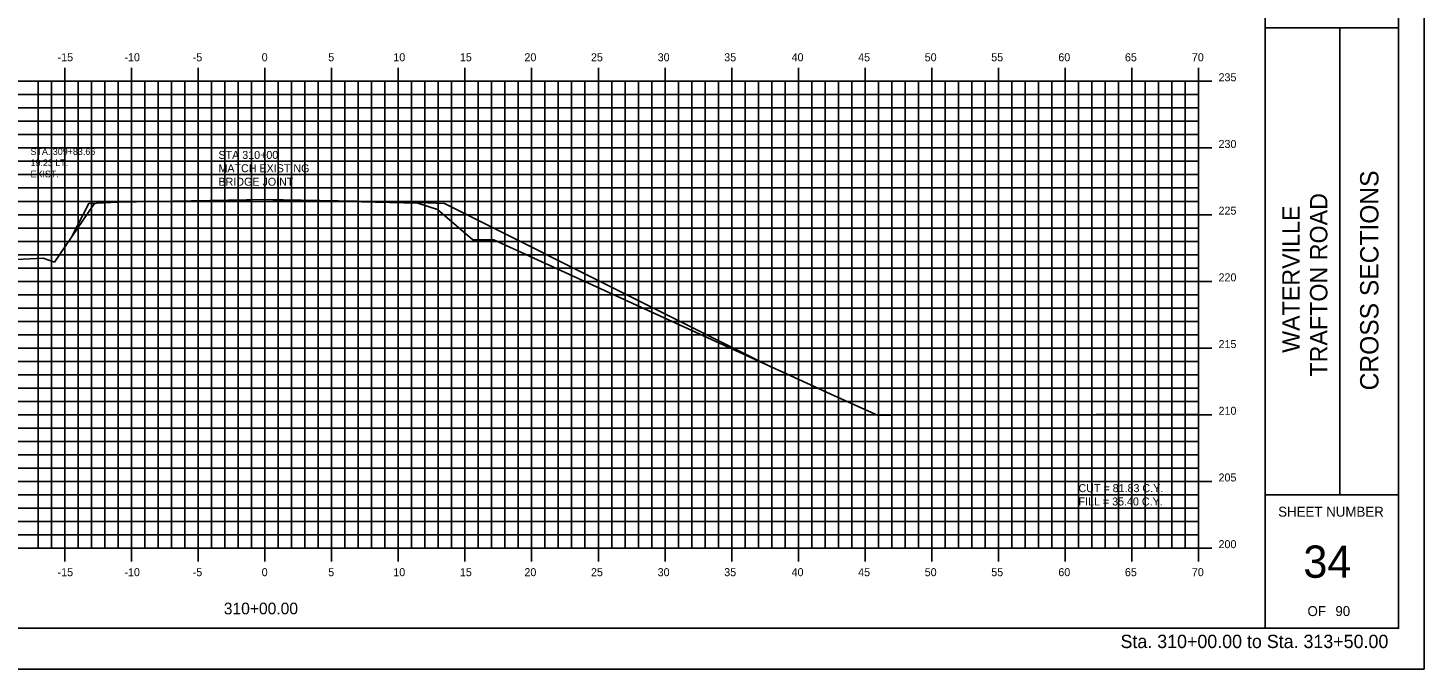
# Model space of a CAD drawing. Extents: x 1138098 to 1138268, y 608981 to 609091.
# Drawn here: x 1138163.2 to 1138267.8, y 608981.3 to 609029.3 of the extents above; entities that cross this region are included whole.
import ezdxf

# ---------------------------------------------------------------- set-up
doc = ezdxf.new("R2010")
doc.units = 0
for name, color, linetype in [('ANNOTATION', 7, 'Continuous'), ('BORDER', 7, 'Continuous'), ('D_Roadway_Centerline', 7, 'Continuous'), ('D_Text_Monospaced', 7, 'Continuous'), ('D_Text_Standard', 7, 'Continuous'), ('H_V ANNOTATION', 7, 'Continuous'), ('HIGHWAY_TITLE', 7, 'Continuous'), ('MAJOR', 7, 'Continuous'), ('MINOR', 7, 'Continuous'), ('PLOT BOUNDARY', 7, 'Continuous'), ('S_Roadway_Centerline', 7, 'Continuous')]:
    doc.layers.add(name, color=color, linetype=linetype)

msp = doc.modelspace()

# ---------------------------------------------------------------- linework, layer by layer
msp.add_lwpolyline([(1138166.45, 609013.7), (1138167.73, 609016.18), (1138167.73, 609016.18), (1138169.92, 609016.27), (1138180.92, 609016.49), (1138191.92, 609016.27), (1138194.38, 609016.17), (1138199.48, 609013.62), (1138204.46, 609011.13), (1138218.9, 609003.91)])
at = {"layer": 'BORDER'}
for p, q in [((1138255.92, 608984.34), (1138255.92, 609089.34)), ((1138255.92, 609029.34), (1138265.92, 609029.34)), ((1138261.51, 608994.34), (1138261.51, 609029.34)), ((1138255.92, 608994.34), (1138265.92, 608994.34))]:
    msp.add_line(p, q, dxfattribs=at)
msp.add_lwpolyline([(1138105.92, 608984.34), (1138265.92, 608984.34), (1138265.92, 609089.34), (1138105.92, 609089.34)], close=True, dxfattribs=at)
at = {"layer": 'MAJOR'}
for p, q in [((1138165.92, 609026.34), (1138165.92, 609025.34)), ((1138170.92, 609026.34), (1138170.92, 609025.34)), ((1138175.92, 609026.34), (1138175.92, 609025.34)), ((1138180.92, 609026.34), (1138180.92, 609025.34)), ((1138185.92, 609026.34), (1138185.92, 609025.34)), ((1138190.92, 609026.34), (1138190.92, 609025.34)), ((1138195.92, 609026.34), (1138195.92, 609025.34)), ((1138200.92, 609026.34), (1138200.92, 609025.34)), ((1138205.92, 609026.34), (1138205.92, 609025.34)), ((1138210.92, 609026.34), (1138210.92, 609025.34)), ((1138215.92, 609026.34), (1138215.92, 609025.34)), ((1138220.92, 609026.34), (1138220.92, 609025.34)), ((1138225.92, 609026.34), (1138225.92, 609025.34)), ((1138230.92, 609026.34), (1138230.92, 609025.34)), ((1138235.92, 609026.34), (1138235.92, 609025.34)), ((1138240.92, 609026.34), (1138240.92, 609025.34)), ((1138245.92, 609026.34), (1138245.92, 609025.34)), ((1138250.92, 609026.34), (1138250.92, 609025.34)), ((1138110.92, 609025.34), (1138250.92, 609025.34)), ((1138110.92, 609025.34), (1138250.92, 609025.34)), ((1138165.92, 608990.34), (1138165.92, 609025.34)), ((1138170.92, 608990.34), (1138170.92, 609025.34)), ((1138175.92, 608990.34), (1138175.92, 609025.34)), ((1138180.92, 608990.34), (1138180.92, 609025.34)), ((1138185.92, 608990.34), (1138185.92, 609025.34)), ((1138190.92, 608990.34), (1138190.92, 609025.34)), ((1138195.92, 608990.34), (1138195.92, 609025.34)), ((1138200.92, 608990.34), (1138200.92, 609025.34)), ((1138205.92, 608990.34), (1138205.92, 609025.34)), ((1138210.92, 608990.34), (1138210.92, 609025.34)), ((1138215.92, 608990.34), (1138215.92, 609025.34)), ((1138220.92, 608990.34), (1138220.92, 609025.34)), ((1138225.92, 608990.34), (1138225.92, 609025.34)), ((1138230.92, 608990.34), (1138230.92, 609025.34)), ((1138235.92, 608990.34), (1138235.92, 609025.34)), ((1138240.92, 608990.34), (1138240.92, 609025.34)), ((1138245.92, 608990.34), (1138245.92, 609025.34)), ((1138251.92, 609025.34), (1138249.92, 609025.34)), ((1138250.92, 608990.34), (1138250.92, 609025.34)), ((1138250.92, 608990.34), (1138250.92, 609025.34)), ((1138110.92, 609020.34), (1138250.92, 609020.34)), ((1138251.92, 609020.34), (1138249.92, 609020.34)), ((1138110.92, 609015.34), (1138250.92, 609015.34)), ((1138251.92, 609015.34), (1138249.92, 609015.34)), ((1138110.92, 609010.34), (1138250.92, 609010.34)), ((1138251.92, 609010.34), (1138249.92, 609010.34)), ((1138110.92, 609005.34), (1138250.92, 609005.34)), ((1138251.92, 609005.34), (1138249.92, 609005.34)), ((1138110.92, 609000.34), (1138250.92, 609000.34)), ((1138251.92, 609000.34), (1138249.92, 609000.34)), ((1138110.92, 608995.34), (1138250.92, 608995.34)), ((1138251.92, 608995.34), (1138249.92, 608995.34)), ((1138110.92, 608990.34), (1138250.92, 608990.34)), ((1138110.92, 608990.34), (1138250.92, 608990.34)), ((1138165.92, 608989.33), (1138165.92, 608990.34)), ((1138170.92, 608989.33), (1138170.92, 608990.34)), ((1138175.92, 608989.33), (1138175.92, 608990.34)), ((1138180.92, 608989.33), (1138180.92, 608990.34)), ((1138185.92, 608989.33), (1138185.92, 608990.34)), ((1138190.92, 608989.33), (1138190.92, 608990.34)), ((1138195.92, 608989.33), (1138195.92, 608990.34)), ((1138200.92, 608989.33), (1138200.92, 608990.34)), ((1138205.92, 608989.33), (1138205.92, 608990.34)), ((1138210.92, 608989.33), (1138210.92, 608990.34)), ((1138215.92, 608989.33), (1138215.92, 608990.34)), ((1138220.92, 608989.33), (1138220.92, 608990.34)), ((1138225.92, 608989.33), (1138225.92, 608990.34)), ((1138230.92, 608989.33), (1138230.92, 608990.34)), ((1138235.92, 608989.33), (1138235.92, 608990.34)), ((1138240.92, 608989.33), (1138240.92, 608990.34)), ((1138245.92, 608989.33), (1138245.92, 608990.34)), ((1138251.92, 608990.34), (1138249.92, 608990.34)), ((1138250.92, 608989.33), (1138250.92, 608990.34))]:
    msp.add_line(p, q, dxfattribs=at)
at = {"layer": 'MINOR'}
for p, q in [((1138163.92, 608990.34), (1138163.92, 609025.34)), ((1138164.92, 608990.34), (1138164.92, 609025.34)), ((1138166.92, 608990.34), (1138166.92, 609025.34)), ((1138167.92, 608990.34), (1138167.92, 609025.34)), ((1138168.92, 608990.34), (1138168.92, 609025.34)), ((1138169.92, 608990.34), (1138169.92, 609025.34)), ((1138171.92, 608990.34), (1138171.92, 609025.34)), ((1138172.92, 608990.34), (1138172.92, 609025.34)), ((1138173.92, 608990.34), (1138173.92, 609025.34)), ((1138174.92, 608990.34), (1138174.92, 609025.34)), ((1138176.92, 608990.34), (1138176.92, 609025.34)), ((1138177.92, 608990.34), (1138177.92, 609025.34)), ((1138178.92, 608990.34), (1138178.92, 609025.34)), ((1138179.92, 608990.34), (1138179.92, 609025.34)), ((1138181.92, 608990.34), (1138181.92, 609025.34)), ((1138182.92, 608990.34), (1138182.92, 609025.34)), ((1138183.92, 608990.34), (1138183.92, 609025.34)), ((1138184.92, 608990.34), (1138184.92, 609025.34)), ((1138186.92, 608990.34), (1138186.92, 609025.34)), ((1138187.92, 608990.34), (1138187.92, 609025.34)), ((1138188.92, 608990.34), (1138188.92, 609025.34)), ((1138189.92, 608990.34), (1138189.92, 609025.34)), ((1138191.92, 608990.34), (1138191.92, 609025.34)), ((1138192.92, 608990.34), (1138192.92, 609025.34)), ((1138193.92, 608990.34), (1138193.92, 609025.34)), ((1138194.92, 608990.34), (1138194.92, 609025.34)), ((1138196.92, 608990.34), (1138196.92, 609025.34)), ((1138197.92, 608990.34), (1138197.92, 609025.34)), ((1138198.92, 608990.34), (1138198.92, 609025.34)), ((1138199.92, 608990.34), (1138199.92, 609025.34)), ((1138201.92, 608990.34), (1138201.92, 609025.34)), ((1138202.92, 608990.34), (1138202.92, 609025.34)), ((1138203.92, 608990.34), (1138203.92, 609025.34)), ((1138204.92, 608990.34), (1138204.92, 609025.34)), ((1138206.92, 608990.34), (1138206.92, 609025.34)), ((1138207.92, 608990.34), (1138207.92, 609025.34)), ((1138208.92, 608990.34), (1138208.92, 609025.34)), ((1138209.92, 608990.34), (1138209.92, 609025.34)), ((1138211.92, 608990.34), (1138211.92, 609025.34)), ((1138212.92, 608990.34), (1138212.92, 609025.34)), ((1138213.92, 608990.34), (1138213.92, 609025.34)), ((1138214.92, 608990.34), (1138214.92, 609025.34)), ((1138216.92, 608990.34), (1138216.92, 609025.34)), ((1138217.92, 608990.34), (1138217.92, 609025.34)), ((1138218.92, 608990.34), (1138218.92, 609025.34)), ((1138219.92, 608990.34), (1138219.92, 609025.34)), ((1138221.92, 608990.34), (1138221.92, 609025.34)), ((1138222.92, 608990.34), (1138222.92, 609025.34)), ((1138223.92, 608990.34), (1138223.92, 609025.34)), ((1138224.92, 608990.34), (1138224.92, 609025.34)), ((1138226.92, 608990.34), (1138226.92, 609025.34)), ((1138227.92, 608990.34), (1138227.92, 609025.34)), ((1138228.92, 608990.34), (1138228.92, 609025.34)), ((1138229.92, 608990.34), (1138229.92, 609025.34)), ((1138231.92, 608990.34), (1138231.92, 609025.34)), ((1138232.92, 608990.34), (1138232.92, 609025.34)), ((1138233.92, 608990.34), (1138233.92, 609025.34)), ((1138234.92, 608990.34), (1138234.92, 609025.34)), ((1138236.92, 608990.34), (1138236.92, 609025.34)), ((1138237.92, 608990.34), (1138237.92, 609025.34)), ((1138238.92, 608990.34), (1138238.92, 609025.34)), ((1138239.92, 608990.34), (1138239.92, 609025.34)), ((1138241.92, 608990.34), (1138241.92, 609025.34)), ((1138242.92, 608990.34), (1138242.92, 609025.34)), ((1138243.92, 608990.34), (1138243.92, 609025.34)), ((1138244.92, 608990.34), (1138244.92, 609025.34)), ((1138246.92, 608990.34), (1138246.92, 609025.34)), ((1138247.92, 608990.34), (1138247.92, 609025.34)), ((1138248.92, 608990.34), (1138248.92, 609025.34)), ((1138249.92, 608990.34), (1138249.92, 609025.34)), ((1138110.92, 609024.34), (1138250.92, 609024.34)), ((1138250.92, 609024.34), (1138249.92, 609024.34)), ((1138110.92, 609023.34), (1138250.92, 609023.34)), ((1138250.92, 609023.34), (1138249.92, 609023.34)), ((1138110.92, 609022.34), (1138250.92, 609022.34)), ((1138250.92, 609022.34), (1138249.92, 609022.34)), ((1138110.92, 609021.34), (1138250.92, 609021.34)), ((1138250.92, 609021.34), (1138249.92, 609021.34)), ((1138110.92, 609019.34), (1138250.92, 609019.34)), ((1138250.92, 609019.34), (1138249.92, 609019.34)), ((1138110.92, 609018.34), (1138250.92, 609018.34)), ((1138250.92, 609018.34), (1138249.92, 609018.34)), ((1138110.92, 609017.34), (1138250.92, 609017.34)), ((1138250.92, 609017.34), (1138249.92, 609017.34)), ((1138110.92, 609016.34), (1138250.92, 609016.34)), ((1138250.92, 609016.34), (1138249.92, 609016.34)), ((1138110.92, 609014.34), (1138250.92, 609014.34)), ((1138250.92, 609014.34), (1138249.92, 609014.34)), ((1138110.92, 609013.34), (1138250.92, 609013.34)), ((1138250.92, 609013.34), (1138249.92, 609013.34)), ((1138110.92, 609012.34), (1138250.92, 609012.34)), ((1138250.92, 609012.34), (1138249.92, 609012.34)), ((1138110.92, 609011.34), (1138250.92, 609011.34)), ((1138250.92, 609011.34), (1138249.92, 609011.34)), ((1138110.92, 609009.34), (1138250.92, 609009.34)), ((1138250.92, 609009.34), (1138249.92, 609009.34)), ((1138110.92, 609008.34), (1138250.92, 609008.34)), ((1138250.92, 609008.34), (1138249.92, 609008.34)), ((1138110.92, 609007.34), (1138250.92, 609007.34)), ((1138250.92, 609007.34), (1138249.92, 609007.34)), ((1138110.92, 609006.34), (1138250.92, 609006.34)), ((1138250.92, 609006.34), (1138249.92, 609006.34)), ((1138110.92, 609004.34), (1138250.92, 609004.34)), ((1138250.92, 609004.34), (1138249.92, 609004.34)), ((1138110.92, 609003.34), (1138250.92, 609003.34)), ((1138250.92, 609003.34), (1138249.92, 609003.34)), ((1138110.92, 609002.34), (1138250.92, 609002.34)), ((1138250.92, 609002.34), (1138249.92, 609002.34)), ((1138110.92, 609001.34), (1138250.92, 609001.34)), ((1138250.92, 609001.34), (1138249.92, 609001.34)), ((1138110.92, 608999.34), (1138250.92, 608999.34)), ((1138250.92, 608999.34), (1138249.92, 608999.34)), ((1138110.92, 608998.34), (1138250.92, 608998.34)), ((1138250.92, 608998.34), (1138249.92, 608998.34)), ((1138110.92, 608997.34), (1138250.92, 608997.34)), ((1138250.92, 608997.34), (1138249.92, 608997.34)), ((1138110.92, 608996.34), (1138250.92, 608996.34)), ((1138250.92, 608996.34), (1138249.92, 608996.34)), ((1138110.92, 608994.34), (1138250.92, 608994.34)), ((1138250.92, 608994.34), (1138249.92, 608994.34)), ((1138110.92, 608993.34), (1138250.92, 608993.34)), ((1138250.92, 608993.34), (1138249.92, 608993.34)), ((1138110.92, 608992.34), (1138250.92, 608992.34)), ((1138250.92, 608992.34), (1138249.92, 608992.34)), ((1138110.92, 608991.34), (1138250.92, 608991.34)), ((1138250.92, 608991.34), (1138249.92, 608991.34))]:
    msp.add_line(p, q, dxfattribs=at)
at = {"layer": 'PLOT BOUNDARY'}
msp.add_lwpolyline([(1138097.83, 608981.28), (1138267.83, 608981.28), (1138267.83, 609091.28), (1138097.83, 609091.28)], close=True, dxfattribs=at)
at = {"layer": 'S_Roadway_Centerline'}
msp.add_lwpolyline([(1138110.92, 609003.16), (1138115.05, 609003.19), (1138120.3, 609003.14), (1138126.71, 609002.99), (1138138.88, 609002.75), (1138154.53, 609008.82), (1138161.27, 609011.94), (1138164.3, 609012.07), (1138165.14, 609011.78), (1138168.12, 609016.15), (1138168.67, 609016.28), (1138177.96, 609016.4), (1138180.85, 609016.49), (1138184.16, 609016.36), (1138186.04, 609016.35), (1138192.39, 609016.2), (1138193.87, 609015.73), (1138196.51, 609013.46), (1138198.08, 609013.45), (1138223.62, 609001.75), (1138226.89, 609000.29), (1138227.92, 609000.31), (1138250.92, 609000.39)], dxfattribs=at)

# ---------------------------------------------------------------- texts
at = {"layer": 'ANNOTATION'}
for s, p in [('STA 310+00', (1138177.44, 609019.52)), ('MATCH EXISTING', (1138177.44, 609018.52)), ('BRIDGE JOINT', (1138177.44, 609017.51))]:
    msp.add_text(s, height=0.6, dxfattribs=at).set_placement(p)
at = {"layer": 'BORDER'}
msp.add_text('CROSS SECTIONS', height=1.3779, rotation=90, dxfattribs=at).set_placement((1138264.41, 609002.17))
for s, height, p in [('SHEET NUMBER', 0.7453, (1138256.89, 608992.7)), ('34', 2.419, (1138258.78, 608988.12)), ('OF', 0.745, (1138259.09, 608985.25)), ('90', 0.745, (1138261.18, 608985.25))]:
    msp.add_text(s, height=height, dxfattribs=at).set_placement(p)
at = {"layer": 'D_Roadway_Centerline'}
for s, p in [('C', (1138180.92, 609016.49)), ('L', (1138180.92, 609016.48))]:
    msp.add_text(s, height=0.0146, dxfattribs=at).set_placement(p)
at = {"layer": 'D_Text_Monospaced'}
for s, p in [('STA. 309+83.66', (1138163.35, 609019.82)), ('19.23 LT.', (1138163.35, 609018.98)), ('EXIST. ', (1138163.35, 609018.14))]:
    msp.add_text(s, height=0.5, dxfattribs=at).set_placement(p)
at = {"layer": 'D_Text_Standard'}
for s, p in [('CUT = 81.83 C.Y.', (1138241.92, 608994.54)), ('FILL = 35.40 C.Y.', (1138241.92, 608993.54))]:
    msp.add_text(s, height=0.6, dxfattribs=at).set_placement(p)
at = {"layer": 'H_V ANNOTATION'}
for s, height, p in [('-15', 0.6, (1138165.38, 609026.84)), ('-10', 0.6, (1138170.39, 609026.84)), ('-5', 0.6, (1138175.51, 609026.84)), ('0', 0.6, (1138180.68, 609026.84)), ('5', 0.6, (1138185.67, 609026.84)), ('10', 0.6, (1138190.55, 609026.84)), ('15', 0.6, (1138195.54, 609026.84)), ('20', 0.6, (1138200.38, 609026.84)), ('25', 0.6, (1138205.37, 609026.84)), ('30', 0.6, (1138210.37, 609026.84)), ('35', 0.6, (1138215.36, 609026.84)), ('40', 0.6, (1138220.41, 609026.84)), ('45', 0.6, (1138225.4, 609026.84)), ('50', 0.6, (1138230.39, 609026.84)), ('55', 0.6, (1138235.38, 609026.84)), ('60', 0.6, (1138240.41, 609026.84)), ('65', 0.6, (1138245.4, 609026.84)), ('70', 0.6, (1138250.42, 609026.84)), ('235', 0.6, (1138252.42, 609025.34)), ('230', 0.6, (1138252.42, 609020.34)), ('225', 0.6, (1138252.42, 609015.34)), ('220', 0.6, (1138252.42, 609010.34)), ('215', 0.6, (1138252.42, 609005.34)), ('210', 0.6, (1138252.42, 609000.34)), ('205', 0.6, (1138252.42, 608995.34)), ('200', 0.6, (1138252.42, 608990.34)), ('-15', 0.6, (1138165.38, 608988.24)), ('-10', 0.6, (1138170.39, 608988.24)), ('-5', 0.6, (1138175.51, 608988.24)), ('0', 0.6, (1138180.68, 608988.24)), ('5', 0.6, (1138185.67, 608988.24)), ('10', 0.6, (1138190.55, 608988.24)), ('15', 0.6, (1138195.54, 608988.24)), ('20', 0.6, (1138200.38, 608988.24)), ('25', 0.6, (1138205.37, 608988.24)), ('30', 0.6, (1138210.37, 608988.24)), ('35', 0.6, (1138215.36, 608988.24)), ('40', 0.6, (1138220.41, 608988.24)), ('45', 0.6, (1138225.4, 608988.24)), ('50', 0.6, (1138230.39, 608988.24)), ('55', 0.6, (1138235.38, 608988.24)), ('60', 0.6, (1138240.41, 608988.24)), ('65', 0.6, (1138245.4, 608988.24)), ('70', 0.6, (1138250.42, 608988.24)), ('310+00.00', 0.875, (1138177.84, 608985.38)), ('Sta. 310+00.00 to Sta. 313+50.00', 1.0002, (1138245.07, 608982.85))]:
    msp.add_text(s, height=height, dxfattribs=at).set_placement(p)
at = {"layer": 'HIGHWAY_TITLE'}
for s, height, p in [('TRAFTON ROAD', 1.3043, (1138260.58, 609003.2)), ('WATERVILLE', 1.304, (1138258.5, 609004.98))]:
    msp.add_text(s, height=height, rotation=90, dxfattribs=at).set_placement(p)
at = {"layer": 'S_Roadway_Centerline'}
for s in ['C', 'L']:
    msp.add_text(s, height=0.0146, dxfattribs=at).set_placement((1138180.84, 609016.49))

doc.saveas('drawing.dxf')
